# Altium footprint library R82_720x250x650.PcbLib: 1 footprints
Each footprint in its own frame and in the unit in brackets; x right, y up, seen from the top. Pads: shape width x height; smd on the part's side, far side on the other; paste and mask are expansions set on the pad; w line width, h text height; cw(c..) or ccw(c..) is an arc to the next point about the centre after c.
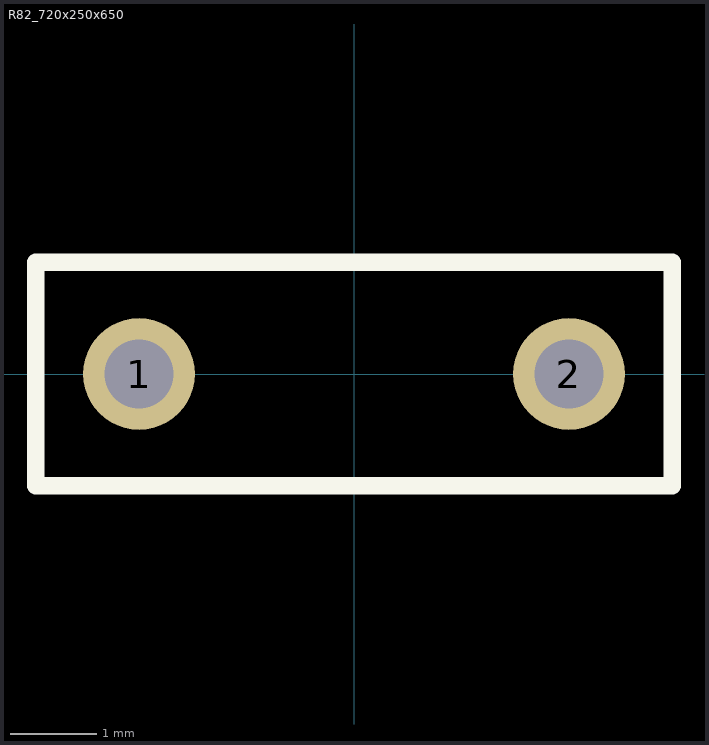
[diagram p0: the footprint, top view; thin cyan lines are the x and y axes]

## R82_720x250x650 [mm] "TH, 2-Leads, Body 7.2x2.5mm, Lead Spacing 5mm"
height 6.6
pads (2):
  round 1.3 hole 0.8: 1(-2.5,0) 2(2.5,0)
Top Overlay:
  lines w0.2: -3.7,-1.3 3.7,-1.3 3.7,1.3 -3.7,1.3 -3.7,-1.3
Mechanical 5:
  lines w0.1: -3.7,-1.3 -3.7,1.3 3.7,1.3 3.7,-1.3 -3.7,-1.3
  text ".Designator" at -1.524,-0.508 h1.02
3D body: height 0, standoff -2.5, extent 2.225,-0.275 2.775,0.275
3D body: height 0, standoff -2.5, extent -2.775,-0.275 -2.225,0.275
3D body: height 6.6, standoff 0, extent -3.7,-1.3 3.7,1.3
